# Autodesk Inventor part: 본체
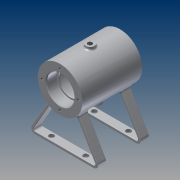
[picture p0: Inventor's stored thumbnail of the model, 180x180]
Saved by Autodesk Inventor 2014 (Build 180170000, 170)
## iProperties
Created: 2016-03
Part Number: 본체
Material: 알루미늄 6061
Document SubType Name: Modeling
Designer: 703-15
Density: 2.71 g/cm^3
Appearance: 알루미늄 - 평지
Mass: 211.809 g
Surface Area: 337.429 cm^2
Volume: 78.1583 cm^3
Author: 703-15
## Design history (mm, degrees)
sketch "스케치1"
  geometry: C1 r 26 at (0, 0); C2 r 16 at (0, 0); 1 further point
  constraints: 2 centre point, 2 coincident
  dimensions: "d0" = 52 diameter of C1; "d1" = 32 diameter of C2
extrude "돌출1" new body sketch "스케치1" stored distance "d2" = 70; taper "d3" = 0 deg
sketch "스케치2"
  geometry: 2 further points
  constraints: 1 vertical alignment
  dimensions: "d4" = 21 distance of point (0, 0) point (0, 21)
hole "구멍1" sketch "스케치2" at (0, 21) diameter "d5" = 3.242; stored, may be unused: countersink angle "d9" = 90 deg, drill point angle "d11" = 118 deg; dims "d6" = 8, "d7" = 4, "d8" = 2, "d10" = 10
node "작업 평면1"
sketch "스케치3"
  geometry: L1 (-16.613, -20)-(-38.264, -57.5); L2 (-33.934, -65)-(33.934, -65); L3 (38.264, -57.5)-(16.613, -20); L4 (0, 26)-(0, -65); L5 (14.183, -21.791)-(35.666, -59); L6 (33.934, -62)-(-33.934, -62); L7 (-35.666, -59)-(-14.183, -21.791); A1 r 26 centre (0, 0) between (-16.613, -20) and (16.613, -20) reference; A2 r 5 centre (-33.934, -60) between (-38.264, -57.5) and (-33.934, -65); A3 r 5 centre (33.934, -60) between (33.934, -65) and (38.264, -57.5); A4 r 2 centre (33.934, -60) between (33.934, -62) and (35.666, -59); A5 r 2 centre (-33.934, -60) between (-35.666, -59) and (-33.934, -62); 3 further points
  constraints: 14 end point, 13 point on circle, 4 centre point, 4 point on line, 4 tangent, 1 equal radius, 1 horizontal, 1 midpoint, 1 perpendicular, 2 other
  dimensions: "d16" = 65 vertical distance of point (42.594, -65) point (0, 0); "d17" = 30 deg angle of L3 L4; "d18" = 30 deg angle of L4 L1; "d19" = 45 vertical distance of L3.end point (42.594, -65); "d20" = 45 vertical distance of point (-42.594, -65) L1.start (= d19); "d21" = 5 radius of A2; "d22" = 3 distance between parallel lines of L3 L5; "d23" = 3 distance between parallel lines of L1 L7; "d24" = 3 distance between parallel lines of L6 L2
extrude "돌출2" join sketch "스케치3" distance "d25" = 10; taper "d26" = 0 deg
sketch "스케치4"
  geometry: C1 r 21 at (0, 0); 1 further point
  constraints: 1 centre point, 1 coincident
  dimensions: "d27" = 42 diameter of C1
extrude "돌출3" cut sketch "스케치4" stored distance "d28" = 42; taper "d29" = 0 deg
node "작업 평면2"
sketch "스케치5"
  geometry: C1 r 14 at (0, 0); C2 r 16 at (0, 0); 1 further point
  constraints: 2 centre point, 2 coincident
  dimensions: "d31" = 28 diameter of C1; "d32" = 32 diameter of C2
extrude "돌출4" join sketch "스케치5" distance "d33" = 2; taper "d34" = 0 deg
fillet "모깎기1" dims "d35" = 0.3, "d46" = 0.5
sketch "스케치6"
  geometry: L1 (0, 10)-(67.868, 10) reference; 3 further points
  constraints: 1 horizontal alignment
  dimensions: "d36" = 20 horizontal distance of point (33.934, -20) point (13.934, 5); "d37" = 20 horizontal distance of point (33.934, -20) point (53.934, 5) (= d36); "d38" = 5 distance from line of L1 point (53.934, 5)
hole "구멍2" sketch "스케치6" at (13.934, 5), (53.934, 5) diameter "d39" = 6; stored, may be unused: countersink angle "d43" = 90 deg, drill point angle "d45" = 118 deg; dims "d40" = 8, "d41" = 4, "d42" = 2, "d44" = 10
node "작업 평면3"
sketch "스케치7"
  geometry: C1 r 5 at (0, 0); 1 further point
  constraints: 1 centre point, 1 coincident
  dimensions: "d48" = 10 diameter of C1
extrude "돌출5" join sketch "스케치7" stored distance "d49" = 2; taper "d50" = 0 deg
hole "구멍3" diameter "d53" = 5.188; stored, may be unused: countersink angle "d57" = 90 deg, drill point angle "d59" = 0 deg; dims "d54" = 6, "d55" = 4, "d56" = 2, "d58" = 10, "d76" = 10, "d77" = 10
sketch "스케치8"
  geometry: C1 r 6 at (0, 0); C2 r 5 at (0, 0) reference; 1 further point
  constraints: 1 centre point, 1 coincident
  dimensions: "d63" = 12 diameter of C1
extrude "돌출6" join sketch "스케치8" stored distance "d64" = 2; taper "d65" = 0 deg
fillet "모깎기2" dims "d66" = 2, "d67" = 3
chamfer "모따기1" distance "d73" = 1; stored, may be unused: second distance "d74" = 2, angle "d75" = 45 deg
node "작업 평면5"
sketch "스케치10"
  geometry: L1 (26, 35)-(-26, 35) reference; L2 (26, -35)-(26, 35) reference; 2 further points
  constraints: 1 coincident, 1 other
feature "엠보싱2" sketch "스케치10" dims "d16" = 65, "d17" = 30 deg, "d18" = 30 deg, "d19" = 45, "d20" = 45 (= d19), "d21" = 5, "d22" = 3, "d23" = 3, "d24" = 3, "d79" = 0.5, "d80" = 0
node "솔리드1"
pattern_circular "원형 패턴1" dims angle "d13" = 360 deg
mirror "대칭1"
mirror "대칭2"
mirror "대칭3"
mirror "대칭4"
pattern_circular "원형 패턴2" dims angle "d61" = -165 deg
other parameters: "d30" = 21, "d47" = 29, "d78" = -26
